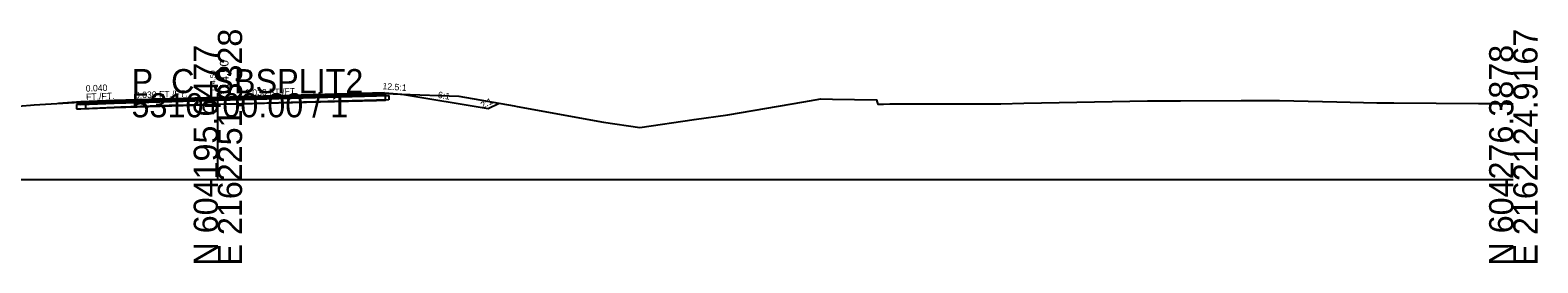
# Model space of a CAD drawing. Extents: x -26 to 1303, y -10 to 12033.
# Drawn here: x 1128.3 to 1302.8, y 2990.3 to 3017.3 of the extents above; entities that cross this region are included whole.
import ezdxf

# ---------------------------------------------------------------- set-up
doc = ezdxf.new("R2010")
doc.units = 0
for name, color, linetype in [('RD_GPK_XS_Cell', 7, 'Continuous'), ('RD_XS_Base', 7, 'Continuous'), ('RD_XS_ExGround', 7, 'Continuous'), ('RD_XS_ExPaveRet', 7, 'Continuous'), ('RD_XS_Greenside', 7, 'Continuous'), ('RD_XS_Pave', 7, 'Continuous'), ('RD_XS_PaveOvlay_CP', 7, 'Continuous'), ('RD_XS_TieSlope', 7, 'Continuous'), ('RD_XS_TX_Elev_EX', 7, 'Continuous'), ('RD_XS_TX_Elev_PR', 7, 'Continuous'), ('RD_XS_TX_ShdSlope', 7, 'Continuous'), ('RD_XS_TX_Slope', 7, 'Continuous')]:
    doc.layers.add(name, color=color, linetype=linetype)

msp = doc.modelspace()

# ---------------------------------------------------------------- linework, layer by layer
at = {"layer": 'RD_GPK_XS_Cell'}
for p, q in [((1150, 3000), (1150, 3010)), ((1000, 3000), (1150, 3000)), ((1150, 3000), (1300, 3000))]:
    msp.add_line(p, q, dxfattribs=at)
at = {"layer": 'RD_XS_Base'}
for p, q in [((1150, 3009.18), (1169.3, 3009.72)), ((1169.3, 3009.72), (1169.3, 3009.72)), ((1169.8, 3009.74), (1169.8, 3009.24)), ((1134.12, 3008.69), (1133.62, 3008.67)), ((1133.62, 3008.67), (1133.62, 3008.67)), ((1133.62, 3008.67), (1133.62, 3008.17)), ((1133.62, 3008.17), (1134.12, 3008.19)), ((1138, 3008.85), (1134.12, 3008.69)), ((1134.12, 3008.69), (1134.12, 3008.69)), ((1134.12, 3008.19), (1138, 3008.35)), ((1134.12, 3008.19), (1134.12, 3008.19)), ((1150, 3009.18), (1138, 3008.85)), ((1138, 3008.85), (1138, 3008.85)), ((1138, 3008.35), (1150, 3008.68)), ((1138, 3008.35), (1138, 3008.35)), ((1150, 3008.68), (1150, 3009.34)), ((1150, 3009.34), (1150, 3009.34)), ((1150, 3009.34), (1150, 3009.34)), ((1150, 3009.34), (1150, 3009.18)), ((1169.8, 3009.24), (1150, 3008.68)), ((1150, 3009.18), (1150, 3009.18)), ((1150, 3008.68), (1150, 3009.18)), ((1150, 3009.18), (1150, 3009.18)), ((1150, 3009.18), (1150, 3009.18)), ((1150, 3008.68), (1150, 3008.68)), ((1162, 3009.52), (1162, 3009.52)), ((1162, 3009.52), (1162, 3009.52)), ((1162, 3009.02), (1162, 3009.02)), ((1162, 3009.02), (1162, 3009.02)), ((1169.8, 3009.7), (1169.8, 3009.7))]:
    msp.add_line(p, q, dxfattribs=at)
at = {"layer": 'RD_XS_ExGround'}
msp.add_lwpolyline([(1125.39, 3008.37), (1128.29, 3008.6), (1128.74, 3008.64), (1134.69, 3008.99), (1138.8, 3009.15), (1144.41, 3009.36), (1146.57, 3009.38), (1149.82, 3009.47), (1149.95, 3009.5), (1150.36, 3009.48), (1150.75, 3009.5), (1152.63, 3009.53), (1155.41, 3009.6), (1168.35, 3009.92), (1169.39, 3009.95), (1171.16, 3009.9), (1177.9, 3009.67), (1184.29, 3008.53), (1184.67, 3008.46), (1194.67, 3006.65), (1198.86, 3006.02), (1205.16, 3006.96), (1209.06, 3007.5), (1217.85, 3009.01), (1219.8, 3009.34), (1221.16, 3009.32), (1226.26, 3009.21), (1226.33, 3008.96), (1226.41, 3008.71), (1227.09, 3008.73), (1227.81, 3008.76), (1235.3, 3008.77), (1240.65, 3008.78), (1243.32, 3008.85), (1257.64, 3009.1), (1261.47, 3009.13), (1268.5, 3009.17), (1268.55, 3009.17), (1271.11, 3009.15), (1272.91, 3009.15), (1279.58, 3008.99), (1284.2, 3008.89), (1286.17, 3008.89), (1295.96, 3008.81), (1297.73, 3008.8), (1299.27, 3008.77), (1300, 3008.77)], dxfattribs=at)
at = {"layer": 'RD_XS_ExPaveRet'}
for points in [[(1169.39, 3009.95), (1168.35, 3009.92), (1168.35, 3009.92), (1155.41, 3009.6), (1155.41, 3009.6), (1152.63, 3009.53), (1152.63, 3009.53), (1150.75, 3009.5), (1150.75, 3009.5), (1150.75, 3009.5), (1150.36, 3009.48), (1150.36, 3009.48), (1149.95, 3009.5), (1149.82, 3009.47), (1149.82, 3009.47), (1149.82, 3009.47), (1146.57, 3009.38), (1146.57, 3009.38), (1144.41, 3009.36), (1144.41, 3009.36), (1138.8, 3009.15), (1138.8, 3009.15), (1134.69, 3008.99), (1134.69, 3008.99), (1134.69, 3008.99), (1134.69, 3008.24), (1134.69, 3008.24), (1138.8, 3008.4), (1138.8, 3008.4), (1144.41, 3008.61), (1144.41, 3008.61), (1146.57, 3008.63), (1146.57, 3008.63), (1149.82, 3008.72), (1149.82, 3008.72), (1149.82, 3008.72), (1149.95, 3008.75), (1150.36, 3008.73), (1150.36, 3008.73), (1150.75, 3008.75), (1150.75, 3008.75), (1150.75, 3008.75), (1152.63, 3008.78), (1152.63, 3008.78), (1155.41, 3008.85), (1155.41, 3008.85), (1168.35, 3009.17), (1168.35, 3009.17), (1169.39, 3009.2), (1169.39, 3009.2), (1169.39, 3009.95), (1169.39, 3009.95), (1169.39, 3009.95)], [(1169.39, 3009.95), (1168.35, 3009.92), (1155.41, 3009.6), (1152.63, 3009.53), (1150.75, 3009.5), (1150.36, 3009.48), (1149.95, 3009.5), (1149.82, 3009.47), (1146.57, 3009.38), (1144.41, 3009.36), (1138.8, 3009.15), (1134.69, 3008.99), (1134.69, 3008.24), (1138.8, 3008.4), (1144.41, 3008.61), (1146.57, 3008.63), (1149.82, 3008.72), (1149.95, 3008.75), (1150.36, 3008.73), (1150.75, 3008.75), (1152.63, 3008.78), (1155.41, 3008.85), (1168.35, 3009.17), (1169.39, 3009.2), (1169.39, 3009.2), (1169.39, 3009.95), (1169.39, 3009.95)]]:
    msp.add_lwpolyline(points, dxfattribs=at)
at = {"layer": 'RD_XS_Greenside'}
for p, q in [((1171.3, 3009.88), (1181.3, 3008.22)), ((1181.3, 3008.22), (1182.56, 3008.84))]:
    msp.add_line(p, q, dxfattribs=at)
at = {"layer": 'RD_XS_Pave'}
for p, q in [((1169.3, 3010.04), (1150, 3009.5)), ((1169.3, 3009.88), (1150, 3009.34)), ((1150, 3009.34), (1169.3, 3009.88)), ((1150, 3009.18), (1169.8, 3009.74)), ((1162, 3009.84), (1162, 3009.84)), ((1162, 3009.84), (1162, 3009.84)), ((1169.3, 3009.88), (1169.3, 3010.04)), ((1169.3, 3010.04), (1169.3, 3010.04)), ((1169.3, 3009.72), (1169.3, 3009.88)), ((1169.3, 3009.88), (1169.3, 3009.88)), ((1138, 3009.17), (1134.12, 3009.01)), ((1134.12, 3009.01), (1134.12, 3009.01)), ((1134.12, 3009.01), (1134.12, 3008.85)), ((1134.12, 3008.85), (1138, 3009.01)), ((1138, 3009.01), (1134.12, 3008.85)), ((1134.12, 3008.85), (1134.12, 3008.85)), ((1134.12, 3008.85), (1134.12, 3008.69)), ((1134.12, 3008.69), (1138, 3008.85)), ((1150, 3009.5), (1138, 3009.17)), ((1138, 3009.01), (1150, 3009.34)), ((1150, 3009.34), (1138, 3009.01)), ((1138, 3008.85), (1150, 3009.18)), ((1138, 3009.17), (1138, 3009.17)), ((1138, 3009.01), (1138, 3009.01)), ((1138, 3009.01), (1138, 3009.01)), ((1138, 3008.85), (1138, 3008.85)), ((1150, 3009.5), (1150, 3009.5)), ((1150, 3009.34), (1150, 3009.34)), ((1150, 3009.34), (1150, 3009.34)), ((1150, 3009.34), (1150, 3009.18)), ((1150, 3009.34), (1150, 3009.34)), ((1150, 3009.18), (1150, 3009.34)), ((1150, 3009.34), (1150, 3009.34)), ((1150, 3009.34), (1150, 3009.34)), ((1150, 3009.18), (1150, 3009.18)), ((1150, 3009.18), (1150, 3009.18)), ((1162, 3009.68), (1162, 3009.68)), ((1162, 3009.68), (1162, 3009.68)), ((1162, 3009.68), (1162, 3009.68)), ((1162, 3009.68), (1162, 3009.68)), ((1162, 3009.52), (1162, 3009.52)), ((1162, 3009.52), (1162, 3009.52))]:
    msp.add_line(p, q, dxfattribs=at)
at = {"layer": 'RD_XS_PaveOvlay_CP'}
for p, q in [((1169.3, 3010.04), (1150, 3009.5)), ((1162, 3009.84), (1162, 3009.84)), ((1162, 3009.84), (1162, 3009.84)), ((1138, 3009.17), (1134.12, 3009.01)), ((1150, 3009.5), (1138, 3009.17)), ((1138, 3009.17), (1138, 3009.17)), ((1150, 3009.5), (1150, 3009.5))]:
    msp.add_line(p, q, dxfattribs=at)
at = {"layer": 'RD_XS_TieSlope'}
for p, q in [((1169.3, 3010.04), (1171.3, 3009.88)), ((1134.12, 3009.01), (1131.55, 3008.81))]:
    msp.add_line(p, q, dxfattribs=at)

# ---------------------------------------------------------------- texts
at = {"layer": 'RD_GPK_XS_Cell'}
for s, p in [('E 2162251.3328', (1152.8, 2990)), ('E 2162124.9167', (1302.8, 2990)), ('N 604195.6477', (1150, 2990)), ('N 604276.3878', (1300, 2990))]:
    msp.add_text(s, height=2.8, rotation=90, dxfattribs=at).set_placement(p)
for s, p in [('P_C_SBSPLIT2', (1140, 3010)), ('5310+00.00 / 1', (1140, 3007.2))]:
    msp.add_text(s, height=2.8, dxfattribs=at).set_placement(p)
at = {"layer": 'RD_XS_TX_Elev_EX'}
msp.add_text('114.50', height=0.6, rotation=90, dxfattribs=at).set_placement((1149.72, 3010.12))
at = {"layer": 'RD_XS_TX_Elev_PR'}
msp.add_text('114.50', height=1, rotation=90, dxfattribs=at).set_placement((1151.23, 3009.76))
at = {"layer": 'RD_XS_TX_ShdSlope'}
msp.add_text('12.5:1', height=0.75, rotation=355.4261, dxfattribs=at).set_placement((1169.04, 3010.47))
at = {"layer": 'RD_XS_TX_Slope'}
for s, rotation, p in [('0.040 ', 2.2906, (1134.71, 3010.17)), ('FT./FT.', 2.2906, (1134.75, 3009.19)), ('0.030 FT./FT.', 1.7184, (1140.41, 3009.4)), ('0.030 FT./FT.', 1.7184, (1153.16, 3009.67)), ('6:1', 350.5358, (1175.43, 3009.47)), ('2:1', 26.5651, (1180.64, 3008.2))]:
    msp.add_text(s, height=0.75, rotation=rotation, dxfattribs=at).set_placement(p)

doc.saveas('drawing.dxf')
